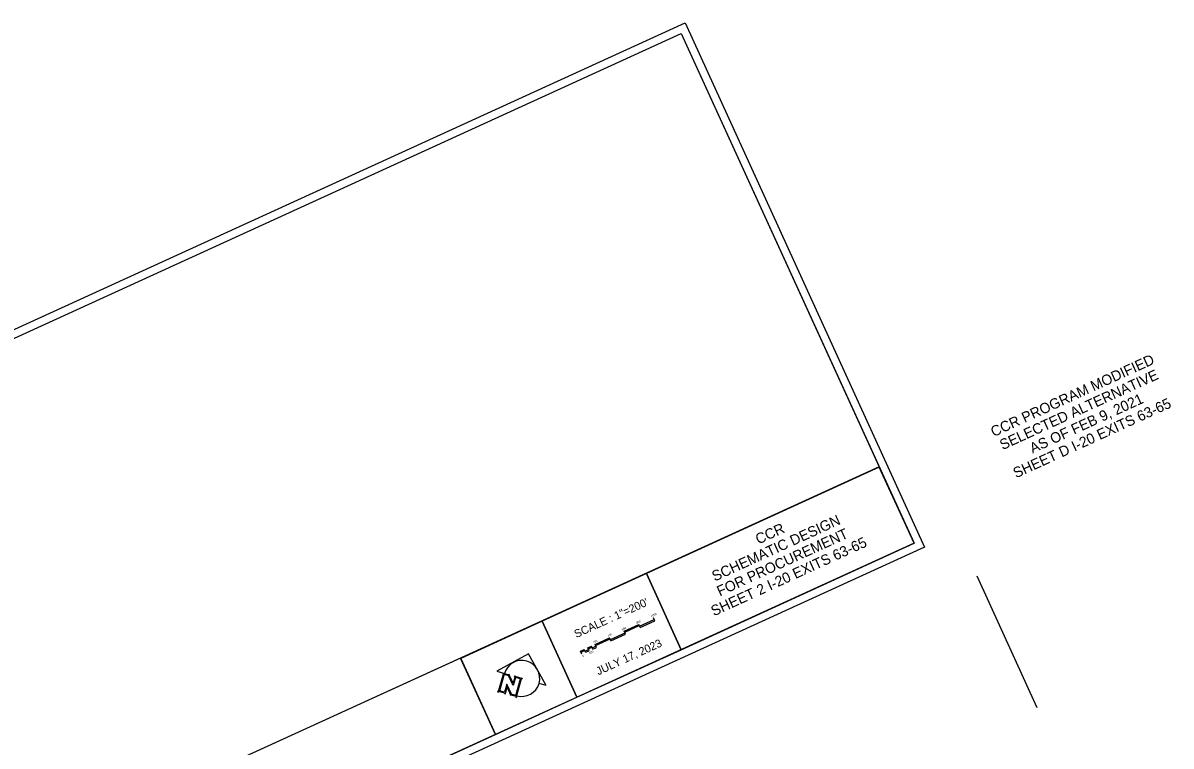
# Model space of a CAD drawing. Extents: x 1952253 to 1982336, y 791177 to 808695.
# Drawn here: x 1967995 to 1982336, y 799664 to 808695 of the extents above; entities that cross this region are included whole.
import ezdxf

# ---------------------------------------------------------------- set-up
doc = ezdxf.new("R2010")
doc.units = 0
for name, color, linetype in [('RD_SHT_Bndy', 7, 'Continuous'), ('RD_SHT_IplotShp', 7, 'Continuous'), ('RD_SHT_ShtClip', 7, 'Continuous'), ('RD_SHT_TX', 7, 'Continuous')]:
    doc.layers.add(name, color=color, linetype=linetype)

msp = doc.modelspace()

# ---------------------------------------------------------------- linework, layer by layer
at = {"layer": 'RD_SHT_Bndy'}
for points in [[(1979125, 802196), (1955294, 791309), (1952386, 797676), (1976217, 808563)], [(1976218, 800867), (1979125, 802196), (1978691, 803147), (1975783, 801819)], [(1974914, 800272), (1976218, 800867), (1975783, 801819), (1974479, 801223)], [(1973897, 799807), (1974914, 800272), (1974479, 801223), (1973463, 800759)], [(1959271, 793126), (1973897, 799807), (1973461, 800762), (1958835, 794081)]]:
    msp.add_lwpolyline(points, close=True, dxfattribs=at)
at = {"layer": 'RD_SHT_IplotShp'}
msp.add_lwpolyline([(1979258, 802146), (1955245, 791177), (1952253, 797726), (1976266, 808695)], close=True, dxfattribs=at)
at = {"layer": 'RD_SHT_ShtClip'}
msp.add_lwpolyline([(1978689, 803151), (1954858, 792264), (1952386, 797676), (1976217, 808563)], close=True, dxfattribs=at)
msp.add_lwpolyline([(1978689, 803151), (1954858, 792264), (1952386, 797676), (1976217, 808563)], close=True, dxfattribs=at)
msp.add_lwpolyline([(1978689, 803151), (1954858, 792264), (1952386, 797676), (1976217, 808563)], close=True, dxfattribs=at)
msp.add_lwpolyline([(1978689, 803151), (1954858, 792264), (1952386, 797676), (1976217, 808563)], close=True, dxfattribs=at)
at = {"layer": 'RD_SHT_TX'}
for p, q in [((1979909, 801788), (1980659, 800145)), ((1975698, 801159), (1975880, 801242)), ((1975704, 801145), (1975886, 801228)), ((1975886, 801228), (1975869, 801265)), ((1975334, 800993), (1975516, 801076)), ((1975505, 801098), (1975687, 801182)), ((1975522, 801062), (1975505, 801098)), ((1975512, 801085), (1975693, 801168)), ((1975704, 801145), (1975687, 801182)), ((1975141, 800932), (1975323, 801015)), ((1975158, 800896), (1975141, 800932)), ((1975148, 800919), (1975330, 801002)), ((1975340, 800979), (1975323, 801015)), ((1975340, 800979), (1975522, 801062)), ((1974310, 800817), (1973913, 800597)), ((1974531, 800420), (1974310, 800817)), ((1974960, 800849), (1975005, 800870)), ((1974976, 800813), (1974960, 800849)), ((1974966, 800836), (1975011, 800856)), ((1975022, 800834), (1975005, 800870)), ((1975015, 800847), (1975061, 800868)), ((1975022, 800834), (1975067, 800854)), ((1975050, 800891), (1975096, 800911)), ((1975067, 800854), (1975050, 800891)), ((1975057, 800877), (1975102, 800898)), ((1975113, 800875), (1975096, 800911)), ((1975106, 800889), (1975152, 800910)), ((1975113, 800875), (1975158, 800896)), ((1973913, 800597), (1974009, 800570)), ((1973997, 800573), (1973928, 800330)), ((1974005, 800560), (1973946, 800354)), ((1974005, 800560), (1974060, 800545)), ((1974008, 800570), (1974076, 800551)), ((1974118, 800419), (1974060, 800545)), ((1974116, 800450), (1974065, 800562)), ((1974142, 800540), (1974116, 800450)), ((1974147, 800520), (1974118, 800419)), ((1974238, 800505), (1974130, 800535)), ((1974210, 800502), (1974147, 800520)), ((1974151, 800296), (1974210, 800502)), ((1974156, 800267), (1974228, 800518)), ((1974225, 800508), (1974225, 800508)), ((1974040, 800436), (1974011, 800335)), ((1974043, 800404), (1974015, 800309)), ((1974099, 800310), (1974040, 800436)), ((1974095, 800291), (1974043, 800404)), ((1974531, 800420), (1974441, 800446)), ((1974027, 800319), (1973923, 800349)), ((1974011, 800335), (1973947, 800354)), ((1974173, 800277), (1974082, 800303)), ((1974151, 800296), (1974094, 800312))]:
    msp.add_line(p, q, dxfattribs=at)
msp.add_arc((1974225, 800508), 225, 253.985, 163.9842, dxfattribs=at)

# ---------------------------------------------------------------- texts
for s, height, p in [('CCR PROGRAM MODIFIED', 130, (1980120, 803522)), ('SELECTED ALTERNATIVE', 130, (1980232, 803359)), ('SHEET D I-20 EXITS 63-65', 130, (1980400, 803007)), ('AS OF FEB 9, 2021', 130, (1980606, 803316)), ('SCHEMATIC DESIGN', 130, (1976637, 801717)), ('FOR PROCUREMENT', 130, (1976699, 801531)), ('CCR', 130, (1977181, 802180)), ('SHEET 2 I-20 EXITS 63-65', 130, (1976625, 801283)), ('SCALE : 1"=200\'', 100, (1974908, 801011)), ('800', 25, (1975662, 801190)), ('1000', 25, (1975844, 801273)), ('600', 25, (1975480, 801107)), ('200', 25, (1975121, 800943)), ('JULY 17, 2023', 100, (1975182, 800546)), ('400', 25, (1975303, 801026)), ('0', 25, (1974989, 800773)), ('100', 25, (1975071, 800811))]:
    msp.add_text(s, height=height, rotation=24.5517, dxfattribs=at).set_placement(p)

doc.saveas('drawing.dxf')
